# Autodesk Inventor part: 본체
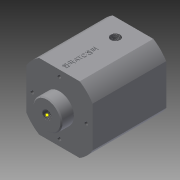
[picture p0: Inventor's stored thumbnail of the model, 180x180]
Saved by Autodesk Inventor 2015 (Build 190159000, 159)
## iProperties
Created: 2020-02
Part Number: 본체
Material: 일반
Document SubType Name: Modeling
Designer: 1026954
Density: 1 g/cm^3
Appearance: 기본값
Mass: 199.119 g
Surface Area: 343.328 cm^2
Volume: 199.119 cm^3
Author: 1026954
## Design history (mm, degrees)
sketch "스케치1"
  geometry: L1 (-32, -32)-(32, -32); L2 (32, -32)-(32, 32); L3 (32, 32)-(-32, 32); L4 (-32, 32)-(-32, -32); L5 (-32, -32)-(32, 32); L6 (32, -32)-(-32, 32); C1 r 37.5 at (0, 0); 1 further point
  constraints: 12 end point, 2 midpoint, 2 parallel, 1 centre point, 1 coincident, 1 horizontal, 1 perpendicular
  dimensions: "d0" = 75 diameter of C1; "d1" = 64 distance of L3.end L2.end; "d2" = 64 distance of L2.end L1.end
extrude "돌출1" new body sketch "스케치1" distance "d3" = 83; taper "d4" = 0 deg
sketch "스케치2" dims "d5" = 75
  geometry: L1 (-32, 32)-(-19.551, 32); L2 (-32, 32)-(32, 32) reference; L3 (-32, 32)-(-32, 19.551); L4 (-32, -32)-(-32, 32) reference; L5 (32, 32)-(19.551, 32); L6 (32, 32)-(32, 19.551); L7 (32, 32)-(32, -32) reference; L8 (32, -32)-(32, -19.551); L9 (32, -32)-(19.551, -32); L10 (32, -32)-(-32, -32) reference; L11 (-32, -32)-(-32, -19.551); L12 (-32, -32)-(-19.551, -32); 2 further points
  constraints: 16 end point, 8 point on line, 1 coincident, 10 other
extrude "돌출2" cut sketch "스케치2" stored distance "d6" = 82; taper "d7" = 0 deg
sketch "스케치3"
  geometry: L1 (32, -32)-(-32, -32); L2 (-32, -32)-(-32, 32); L3 (-32, 32)-(32, 32); L4 (32, 32)-(32, -32); L5 (32, -32)-(-32, 32); L6 (-32, -32)-(32, 32); C1 r 14 at (0, 0); C2 r 37.5 at (0, 0); 1 further point
  constraints: 12 end point, 2 centre point, 2 coincident, 2 midpoint, 2 parallel, 1 horizontal, 1 perpendicular
  dimensions: "d8" = 28 diameter of C1; "d9" = 75 diameter of C2; "d10" = 64 distance of L2.end L3.end; "d11" = 64 distance of L1.end L2.end
extrude "돌출3" cut sketch "스케치3" distance "d12" = 12; taper "d13" = 0 deg
sketch "스케치4"
  geometry: C1 r 14 at (0, 0) reference; 1 further point
hole "구멍1" sketch "스케치4" at (0, 0) diameter "d14" = 8.917; stored, may be unused: countersink angle "d18" = 90 deg, drill point angle "d20" = 118 deg; dims "d15" = 14, "d16" = 4, "d17" = 2, "d19" = 17
sketch "스케치5"
  geometry: C1 r 4.458 at (0, 0) reference; C2 r 14 at (0, 0) reference; C3 r 2 at (0, 0); 1 further point
  constraints: 1 centre point, 1 coincident
  dimensions: "d21" = 4 diameter of C3
extrude "돌출4" cut sketch "스케치5" stored distance "d22" = 12; taper "d23" = 0 deg
sketch "스케치6"
  geometry: L1 (0, 0)-(0, 26)
  constraints: 2 end point, 1 vertical
  dimensions: "d24" = 26 distance of L1.start L1.end
hole "구멍2" sketch "스케치6" at (0, 26) diameter "d25" = 3.459; stored, may be unused: countersink angle "d29" = 90 deg, drill point angle "d31" = 118 deg; dims "d26" = 10, "d27" = 4, "d28" = 2, "d30" = 12
sketch "스케치7"
  geometry: L1 (39.102, -71)-(0, -71) reference; L2 (0, -71)-(0, 0) reference; L3 (0, 0)-(39.102, 0) reference; L4 (39.102, 0)-(39.102, -71) reference; L5 (19.551, 0)-(19.551, -17); 1 further point
  constraints: 2 end point, 1 midpoint, 1 vertical
  dimensions: "d35" = 17 distance of L5.start L5.end
hole "구멍3" sketch "스케치7" at (19.551, -17) diameter "d36" = 8.917; stored, may be unused: countersink angle "d40" = 90 deg, drill point angle "d42" = 118 deg; dims "d37" = 6, "d38" = 4, "d39" = 2, "d41" = 9
sketch "스케치8"
  geometry: L1 (39.102, -71)-(0, -71) reference; L2 (0, -71)-(0, 0) reference; L3 (0, 0)-(39.102, 0) reference; L4 (39.102, 0)-(39.102, -71) reference; C1 r 4.458 at (19.551, -17) reference; C2 r 2 at (19.551, -17); 1 further point
  constraints: 1 centre point, 1 coincident
  dimensions: "d43" = 4 diameter of C2
extrude "돌출5" cut sketch "스케치8" distance "d44" = 40; taper "d45" = 0 deg
sketch "스케치9"
  geometry: C1 r 20 at (0, 0); 1 further point
  constraints: 1 centre point, 1 coincident
  dimensions: "d46" = 40 diameter of C1
extrude "돌출6" cut sketch "스케치9" distance "d47" = 62; taper "d48" = 0 deg
sketch "스케치10"
  geometry: L1 (0, 0)-(0, -21.224); L2 (0, 0)-(22.517, -13); L3 (0, 0)-(-22.517, -13); L4 (0, 0)-(0, 26); C1 r 1.73 at (0, 26) reference; A1 r 26 centre (0, 0) between (22.517, -13) and (-22.517, -13)
  constraints: 8 end point, 2 point on circle, 2 vertical, 1 centre point, 1 coincident
  dimensions: "d49" = 52 diameter of A1; "d50" = 60 deg angle of L1 L2; "d51" = 60 deg angle of L1 L3
hole "구멍4" sketch "스케치10" at (22.517, -13), (-22.517, -13), (0, 26) diameter "d52" = 3.459; stored, may be unused: countersink angle "d56" = 90 deg, drill point angle "d58" = 118 deg; dims "d53" = 10, "d54" = 4, "d55" = 2, "d57" = 12
sketch "스케치11"
  geometry: L1 (5.551, -71)-(33.551, -71) reference; L2 (5.551, -83)-(33.551, -83) reference; L3 (0, -71)-(39.102, -71) reference; L4 (39.102, -71)-(39.102, 0) reference; L5 (0, 0)-(39.102, 0) reference; L6 (0, 0)-(0, -71) reference; C1 r 4.458 at (19.551, -17) reference; 3 further points
  constraints: 1 midpoint, 1 vertical alignment, 1 other
  dimensions: "d59" = 20 distance from line of L1 point (19.551, -51)
feature "엠보싱1" sketch "스케치11" dims "d0" = 75, "d1" = 64, "d2" = 64, "d60" = 0.5, "d61" = 0
chamfer "모따기2" distance "d65" = 1.8; stored, may be unused: second distance "d66" = 2, angle "d67" = 15 deg
chamfer "모따기3" distance "d68" = 1; stored, may be unused: second distance "d69" = 2, angle "d70" = 45 deg
sketch "스케치12"
  geometry: 1 further point
node "솔리드1"
pattern_circular "원형 패턴1" dims angle "d33" = 360 deg
node "투영된 루프1"
node "투영된 루프2"
node "절단 모서리 투영1"
node "절단 모서리 투영2"
node "절단 모서리 투영3"
node "절단 모서리 투영4"
